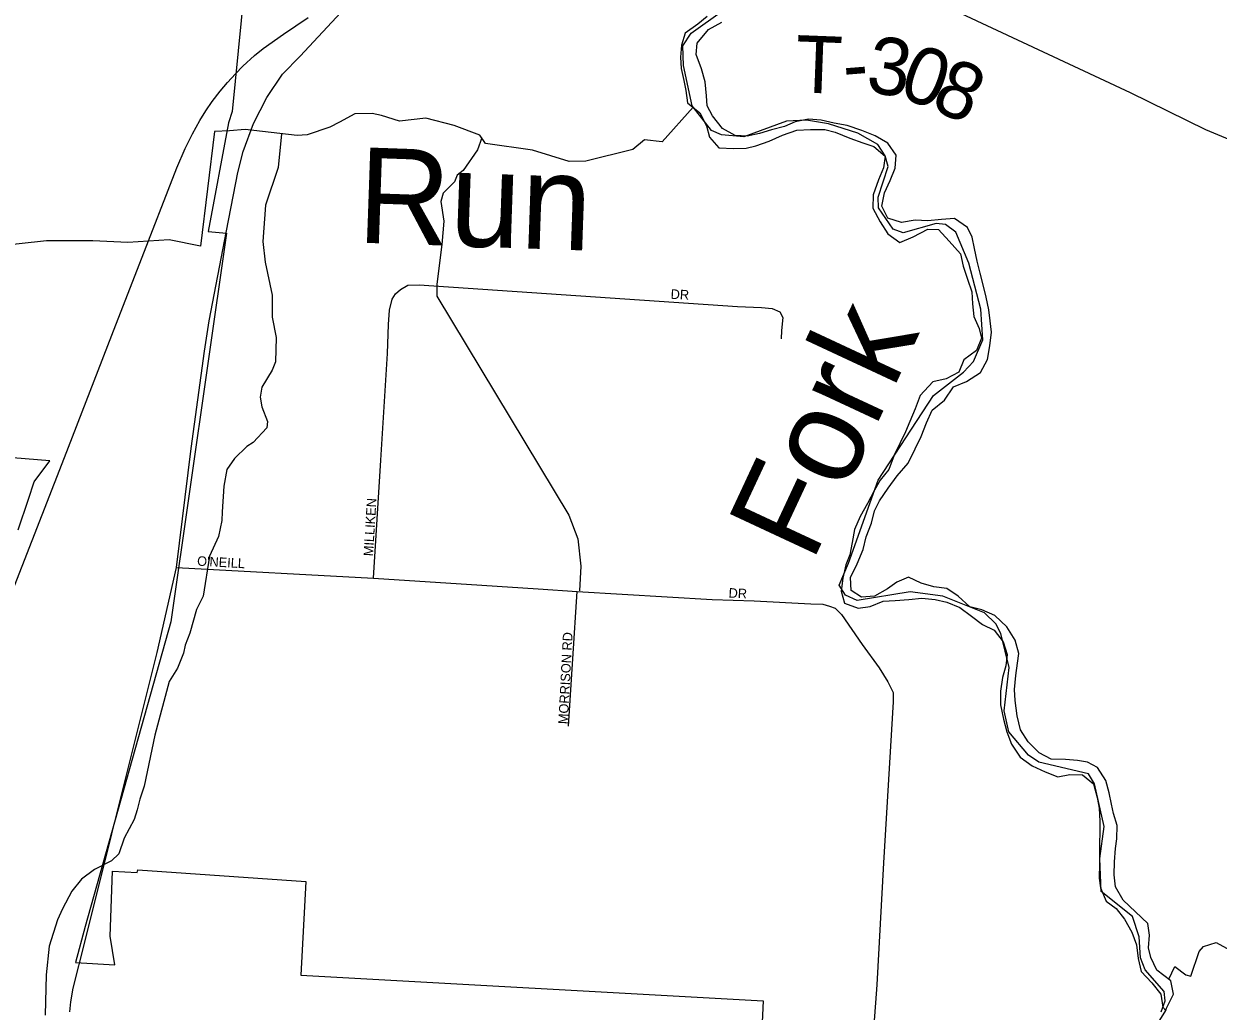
# Model space of a CAD drawing. Extents: x 0 to 40.4, y 0 to 22.
# Drawn here: x 6.701 to 7.886, y 17.952 to 18.932 of the extents above; entities that cross this region are included whole.
import ezdxf

# ---------------------------------------------------------------- set-up
doc = ezdxf.new("R2010")
doc.units = 0
for name, color, linetype in [('GM_X_Corporation', 7, 'Continuous'), ('GM_X_Major_River', 7, 'Continuous'), ('GM_X_Major_River_Text', 7, 'Continuous'), ('GM_X_Minor_River', 7, 'Continuous'), ('GM_X_Minor_River_Text', 7, 'Continuous'), ('GM_X_Rail_Line', 7, 'Continuous'), ('GM_X_State_Route', 7, 'Continuous'), ('GM_X_Township', 7, 'Continuous'), ('GM_X_Township_Road', 7, 'Continuous'), ('GM_X_Township_Road_Text', 7, 'Continuous'), ('GM_X_Township_Subdivision', 7, 'Continuous'), ('GM_X_Township_Subdivision_Text', 7, 'Continuous')]:
    doc.layers.add(name, color=color, linetype=linetype)

msp = doc.modelspace()

# ---------------------------------------------------------------- linework, layer by layer
at = {"layer": 'GM_X_Corporation'}
for points in [[(6.5092, 19.0041), (6.932, 19.0891), (6.9079, 18.8445), (6.9043, 18.8333), (6.884, 18.7254), (6.9024, 18.7239), (6.847, 18.3381), (6.762, 18.0358), (6.7525, 17.9998), (6.7914, 17.9976), (6.7869, 18.0259), (6.7892, 18.0906), (6.8137, 18.0894), (6.8144, 18.0919), (6.981, 18.0803), (6.9762, 17.9874), (7.435, 17.962), (7.431, 17.8767)], [(6.6956, 18.4294), (6.7057, 18.4599), (6.7114, 18.477), (6.7268, 18.4978), (6.3873, 18.5253)]]:
    msp.add_lwpolyline(points, dxfattribs=at)
at = {"layer": 'GM_X_Major_River'}
for points in [[(7.3795, 18.939), (7.37, 18.9314), (7.3575, 18.9224), (7.354, 18.9106), (7.3528, 18.8985), (7.3535, 18.8875), (7.3561, 18.8753), (7.358, 18.8655), (7.3598, 18.8533), (7.3719, 18.8434), (7.3786, 18.8305), (7.3816, 18.8191), (7.391, 18.8085), (7.4058, 18.808), (7.4179, 18.8084), (7.4277, 18.8106)], [(7.4433, 18.8265), (7.4312, 18.8227), (7.4191, 18.8201), (7.407, 18.8209), (7.3945, 18.8278), (7.3847, 18.8404), (7.3795, 18.8502), (7.3788, 18.8601), (7.3773, 18.8741), (7.3736, 18.887), (7.3683, 18.9011), (7.3695, 18.9124), (7.3806, 18.9261), (7.3938, 18.9332)], [(7.8345, 17.9522), (7.8352, 17.9545), (7.8421, 17.9685), (7.8395, 17.9818), (7.8256, 17.9924), (7.8196, 18.005), (7.8173, 18.0145), (7.8185, 18.027), (7.8167, 18.0387), (7.8046, 18.0501), (7.7922, 18.0619), (7.7847, 18.0749), (7.7832, 18.087), (7.7836, 18.0999), (7.7845, 18.1132), (7.786, 18.1226), (7.7864, 18.1359), (7.7827, 18.1477), (7.7805, 18.1571), (7.7783, 18.1685), (7.7749, 18.1807), (7.7666, 18.1936), (7.7568, 18.1989), (7.747, 18.2005), (7.7349, 18.2013), (7.7209, 18.2017), (7.7088, 18.2082), (7.6979, 18.2189), (7.6904, 18.231), (7.6871, 18.2447), (7.6849, 18.2599), (7.6845, 18.2709), (7.6857, 18.2849), (7.6873, 18.297), (7.6888, 18.3065), (7.6851, 18.3198), (7.6768, 18.3331), (7.6648, 18.3445), (7.652, 18.3499), (7.6402, 18.3529), (7.6286, 18.3636), (7.6173, 18.3712), (7.6044, 18.3728), (7.5916, 18.3766), (7.5791, 18.3824), (7.5677, 18.3775), (7.5583, 18.3707), (7.5454, 18.3635), (7.5325, 18.3625), (7.5223, 18.3693), (7.5216, 18.3822), (7.5281, 18.3958), (7.5342, 18.4098), (7.5373, 18.4223), (7.5426, 18.436), (7.5453, 18.4481), (7.5503, 18.4583), (7.559, 18.4708), (7.5678, 18.4829), (7.5788, 18.4957), (7.5857, 18.5097), (7.5918, 18.5222), (7.5971, 18.5355), (7.6025, 18.5483), (7.615, 18.5582), (7.6237, 18.5714), (7.6366, 18.5766), (7.6507, 18.5857), (7.6575, 18.5986), (7.6598, 18.6122), (7.6614, 18.6255), (7.6603, 18.6368), (7.6589, 18.6478), (7.6563, 18.6604), (7.6537, 18.6714), (7.6503, 18.6843), (7.6473, 18.696), (7.6447, 18.7086), (7.6425, 18.7199), (7.6376, 18.7294), (7.6248, 18.7386), (7.612, 18.7375), (7.5983, 18.736), (7.5859, 18.7368), (7.5722, 18.7346), (7.5586, 18.7388), (7.5526, 18.7506), (7.5553, 18.7639), (7.5611, 18.776), (7.566, 18.7885), (7.5668, 18.8014), (7.5586, 18.8131), (7.5461, 18.8204), (7.5329, 18.8258), (7.5182, 18.8307), (7.5053, 18.8331), (7.4925, 18.8361), (7.48, 18.837), (7.4668, 18.8344), (7.4562, 18.8298), (7.4433, 18.8265)], [(7.4277, 18.8106), (7.441, 18.8151), (7.4542, 18.8211), (7.4682, 18.826), (7.4819, 18.8267), (7.4962, 18.8267), (7.5064, 18.8243), (7.5208, 18.8182), (7.534, 18.8136), (7.5446, 18.8098), (7.5559, 18.8003), (7.5543, 18.7889), (7.5493, 18.7768), (7.544, 18.762), (7.5439, 18.7487), (7.5511, 18.7351), (7.5586, 18.7233), (7.5706, 18.7145), (7.5839, 18.7202), (7.5983, 18.7277), (7.6089, 18.7276), (7.6194, 18.7159), (7.6307, 18.7033), (7.6333, 18.6912), (7.6378, 18.6782), (7.6419, 18.6657), (7.6426, 18.6536), (7.6441, 18.6411), (7.6493, 18.6293), (7.6516, 18.6198), (7.6466, 18.6073), (7.6341, 18.5983), (7.6291, 18.5858), (7.6166, 18.5794), (7.6033, 18.5764), (7.5908, 18.5628), (7.5858, 18.5495), (7.5805, 18.5371), (7.5763, 18.5268), (7.571, 18.5159), (7.5649, 18.5034), (7.5595, 18.4894), (7.5511, 18.4788), (7.5454, 18.4689), (7.5386, 18.4557), (7.5313, 18.4425), (7.5256, 18.4296), (7.5233, 18.4167), (7.521, 18.4046), (7.5171, 18.3947), (7.5141, 18.3815), (7.5125, 18.3686), (7.5155, 18.3565), (7.5291, 18.3515), (7.5412, 18.3533), (7.554, 18.3586), (7.5658, 18.3593), (7.5794, 18.3604), (7.5923, 18.3615), (7.6055, 18.3603), (7.6172, 18.3576), (7.63, 18.3522), (7.6417, 18.3438), (7.6526, 18.3355), (7.6643, 18.3297), (7.673, 18.3183), (7.6771, 18.3058), (7.6759, 18.2944), (7.6725, 18.2827), (7.6705, 18.2694), (7.6705, 18.2558), (7.6734, 18.2414), (7.6768, 18.2288), (7.6813, 18.2167), (7.6899, 18.2038), (7.702, 18.195), (7.7148, 18.1892), (7.7273, 18.1843), (7.7394, 18.1865), (7.7519, 18.1861), (7.7628, 18.1773), (7.7665, 18.1636), (7.7684, 18.153), (7.7691, 18.1401), (7.769, 18.1303), (7.7686, 18.117), (7.7686, 18.1071), (7.7689, 18.0977), (7.7685, 18.0836), (7.7696, 18.0742), (7.7755, 18.0609), (7.7853, 18.0536), (7.7936, 18.043), (7.8008, 18.0301), (7.8056, 18.0175), (7.8071, 18.0039), (7.81, 17.991), (7.8206, 17.9799), (7.8296, 17.9685), (7.8315, 17.9556), (7.8345, 17.9522)], [(7.8269, 17.9401), (7.8345, 17.9522)]]:
    msp.add_lwpolyline(points, dxfattribs=at)
at = {"layer": 'GM_X_Minor_River'}
for points in [[(7.3653, 18.8488), (7.3347, 18.8145), (7.3173, 18.8164), (7.3056, 18.807), (7.259, 18.7953), (7.2424, 18.795), (7.2061, 18.8064), (7.1593, 18.8129), (7.1536, 18.8213), (7.1283, 18.8308), (7.1, 18.8381), (7.0739, 18.8351), (7.0561, 18.8408), (7.047, 18.8427), (7.0296, 18.8424), (7.0145, 18.8341), (7.0047, 18.8292), (6.9823, 18.8216), (6.9725, 18.8209), (6.9207, 18.8267), (6.9052, 18.8256), (6.8905, 18.8248), (6.8766, 18.7111), (6.8453, 18.7172), (6.8044, 18.7147), (6.7696, 18.7162), (6.7235, 18.7163), (6.666, 18.71)], [(6.957, 18.8226), (6.9535, 18.7891), (6.941, 18.7516), (6.9383, 18.7155), (6.9405, 18.6951), (6.9476, 18.6624), (6.9476, 18.6405), (6.9517, 18.6204), (6.9509, 18.5961), (6.9475, 18.5878), (6.9372, 18.5711), (6.9357, 18.5612), (6.9372, 18.5514), (6.9428, 18.537), (6.9424, 18.5305), (6.9288, 18.5161), (6.9224, 18.512), (6.9102, 18.5002), (6.9026, 18.4893), (6.8996, 18.4726), (6.898, 18.4472), (6.8976, 18.4388), (6.8942, 18.4229), (6.8855, 18.4032), (6.879, 18.3634), (6.8725, 18.3502), (6.866, 18.3267), (6.8611, 18.3149), (6.8596, 18.307), (6.8535, 18.2922), (6.8455, 18.279), (6.831, 18.2255), (6.8204, 18.1751), (6.8162, 18.1622), (6.8135, 18.1516), (6.8105, 18.1418), (6.8006, 18.1232), (6.7953, 18.1077), (6.7881, 18.1009), (6.7714, 18.0922), (6.7585, 18.0827), (6.7487, 18.0706), (6.7396, 18.0532), (6.7346, 18.0422), (6.7263, 18.0161), (6.7232, 17.9876), (6.7224, 17.9478)], [(7.1556, 18.8184), (7.1513, 18.8065), (7.1373, 18.7861), (7.1312, 18.7815), (7.1286, 18.7747), (7.1172, 18.7637), (7.1149, 18.7554), (7.1179, 18.7357), (7.116, 18.7126), (7.111, 18.6731), (7.1109, 18.6614), (7.2421, 18.4439), (7.2511, 18.4204), (7.2541, 18.3934), (7.2525, 18.3688)], [(7.8374, 17.9834), (7.8435, 17.9961), (7.8544, 17.9877), (7.8594, 17.9862), (7.8677, 18.0108), (7.8719, 18.0158), (7.8844, 18.0199), (7.8983, 18.0123)]]:
    msp.add_lwpolyline(points, dxfattribs=at)
at = {"layer": 'GM_X_Rail_Line'}
msp.add_lwpolyline([(6.677, 18.3363), (6.7413, 18.5013), (6.7925, 18.633), (6.8162, 18.6942), (6.8529, 18.7888), (6.8613, 18.8078), (6.8686, 18.8224), (6.8758, 18.8356), (6.8819, 18.8454), (6.8881, 18.8545), (6.8961, 18.8647), (6.9032, 18.8734), (6.9111, 18.8822), (6.9186, 18.8896), (6.9302, 18.9001), (6.9386, 18.9072), (6.9587, 18.9213), (6.9833, 18.9381)], dxfattribs=at)
at = {"layer": 'GM_X_State_Route'}
for points in [[(6.9023, 18.7262), (6.9134, 18.784), (6.9189, 18.8049), (6.929, 18.8329), (6.9422, 18.8585), (6.9577, 18.8818), (6.9755, 18.8996), (7.0156, 18.9428), (7.0587, 18.9862), (7.1121, 19.0405), (7.1614, 19.0909), (7.1881, 19.1176), (7.1892, 19.1185)], [(6.7885, 18.1276), (6.8335, 18.3077), (6.8527, 18.392), (6.8671, 18.51), (6.8803, 18.6069), (6.885, 18.6368), (6.9023, 18.7262)], [(6.7616, 18.02), (6.7885, 18.1276)], [(6.7466, 17.9511), (6.7479, 17.9609), (6.7502, 17.9746), (6.7616, 18.02)]]:
    msp.add_lwpolyline(points, dxfattribs=at)
at = {"layer": 'GM_X_Township'}
msp.add_lwpolyline([(7.8298, 17.9511), (7.8338, 17.9618), (7.8329, 17.9713), (7.814, 17.9927), (7.8096, 18.0044), (7.8082, 18.0253), (7.8014, 18.0457), (7.7703, 18.0703), (7.769, 18.1033), (7.7735, 18.1349), (7.7637, 18.1773), (7.7579, 18.1871), (7.7084, 18.1989), (7.6984, 18.2056), (7.6787, 18.2288), (7.6742, 18.2497), (7.6792, 18.2927), (7.6707, 18.3264), (7.6657, 18.3362), (7.6545, 18.347), (7.6132, 18.3635), (7.5809, 18.3679), (7.5283, 18.3591), (7.5168, 18.3647), (7.5102, 18.3744), (7.5197, 18.3962), (7.5492, 18.4788), (7.6041, 18.5628), (7.6338, 18.586), (7.6438, 18.5965), (7.653, 18.6179), (7.651, 18.6486), (7.6389, 18.694), (7.6263, 18.725), (7.616, 18.7324), (7.6065, 18.7334), (7.574, 18.7242), (7.564, 18.7278), (7.5493, 18.7489), (7.5491, 18.7595), (7.5589, 18.7901), (7.5561, 18.8007), (7.5487, 18.8119), (7.5288, 18.823), (7.4998, 18.8325), (7.4778, 18.8359), (7.458, 18.8349), (7.4158, 18.8194), (7.3937, 18.8214), (7.3838, 18.8258), (7.3644, 18.8502), (7.3558, 18.8903), (7.3552, 18.9097), (7.3633, 18.9223), (7.3945, 18.9445)], dxfattribs=at)
at = {"layer": 'GM_X_Township_Road'}
msp.add_lwpolyline([(7.4485, 18.9846), (7.4569, 18.9777), (7.4727, 18.9663), (7.4798, 18.9609), (7.4907, 18.9597), (7.4969, 18.9609), (7.5051, 18.9648), (7.5194, 18.9743), (7.5266, 18.9782), (7.5354, 18.9816), (7.5403, 18.9825), (7.5489, 18.981), (7.5634, 18.9747), (7.5808, 18.9659), (7.6061, 18.9538), (7.7991, 18.8636), (7.8738, 18.8268), (7.9375, 18.8004)], dxfattribs=at)
at = {"layer": 'GM_X_Township_Subdivision'}
for points in [[(7.0481, 18.3814), (7.0555, 18.4984), (7.062, 18.6045), (7.0629, 18.6331), (7.0642, 18.6473), (7.0667, 18.6585), (7.07, 18.6638), (7.0748, 18.6681), (7.0823, 18.6722), (7.0936, 18.6725), (7.4096, 18.6511), (7.4333, 18.6501), (7.444, 18.6491), (7.4514, 18.6457), (7.4544, 18.6401), (7.4531, 18.6274), (7.4527, 18.619)], [(6.8527, 18.392), (7.0481, 18.3814), (7.1558, 18.3744), (7.2117, 18.3707)], [(7.2117, 18.3707), (7.2503, 18.3682), (7.3843, 18.3604), (7.426, 18.3588), (7.4821, 18.356), (7.4942, 18.3555), (7.5008, 18.3537), (7.5063, 18.3516), (7.5126, 18.3453), (7.5331, 18.3155), (7.5501, 18.2924), (7.5587, 18.2786), (7.5639, 18.268), (7.5639, 18.2587), (7.5542, 18.099), (7.5476, 17.9778), (7.5446, 17.9376)], [(7.2417, 18.2345), (7.2503, 18.3682)]]:
    msp.add_lwpolyline(points, dxfattribs=at)

# ---------------------------------------------------------------- texts
at = {"layer": 'GM_X_Major_River_Text'}
msp.add_text('Fork', height=0.09469, rotation=64.9981, dxfattribs=at).set_placement((7.4834, 18.3957))
at = {"layer": 'GM_X_Minor_River_Text'}
msp.add_text('Run', height=0.09469, rotation=357.9996, dxfattribs=at).set_placement((7.0313, 18.7146))
at = {"layer": 'GM_X_Township_Road_Text'}
for s, rotation, p in [('T', 357.8267, (7.466, 18.8638)), ('3', 351.7912, (7.5357, 18.8643)), ('0', 339.9916, (7.5673, 18.86)), ('8', 335.7046, (7.5992, 18.8485)), ('-', 4.5997, (7.5158, 18.8623))]:
    msp.add_text(s, height=0.0568, rotation=rotation, dxfattribs=at).set_placement(p)
at = {"layer": 'GM_X_Township_Subdivision_Text'}
for s, rotation, p in [('DR', 356.989, (7.3429, 18.6588)), ('MILLIKEN', 86.5853, (7.0477, 18.403)), ("O'NEILL", 356.7581, (6.8729, 18.3939)), ('DR', 356.989, (7.4004, 18.3622)), ('MORRISON RD', 87.0178, (7.241, 18.2363))]:
    msp.add_text(s, height=0.00947, rotation=rotation, dxfattribs=at).set_placement(p)

doc.saveas('drawing.dxf')
